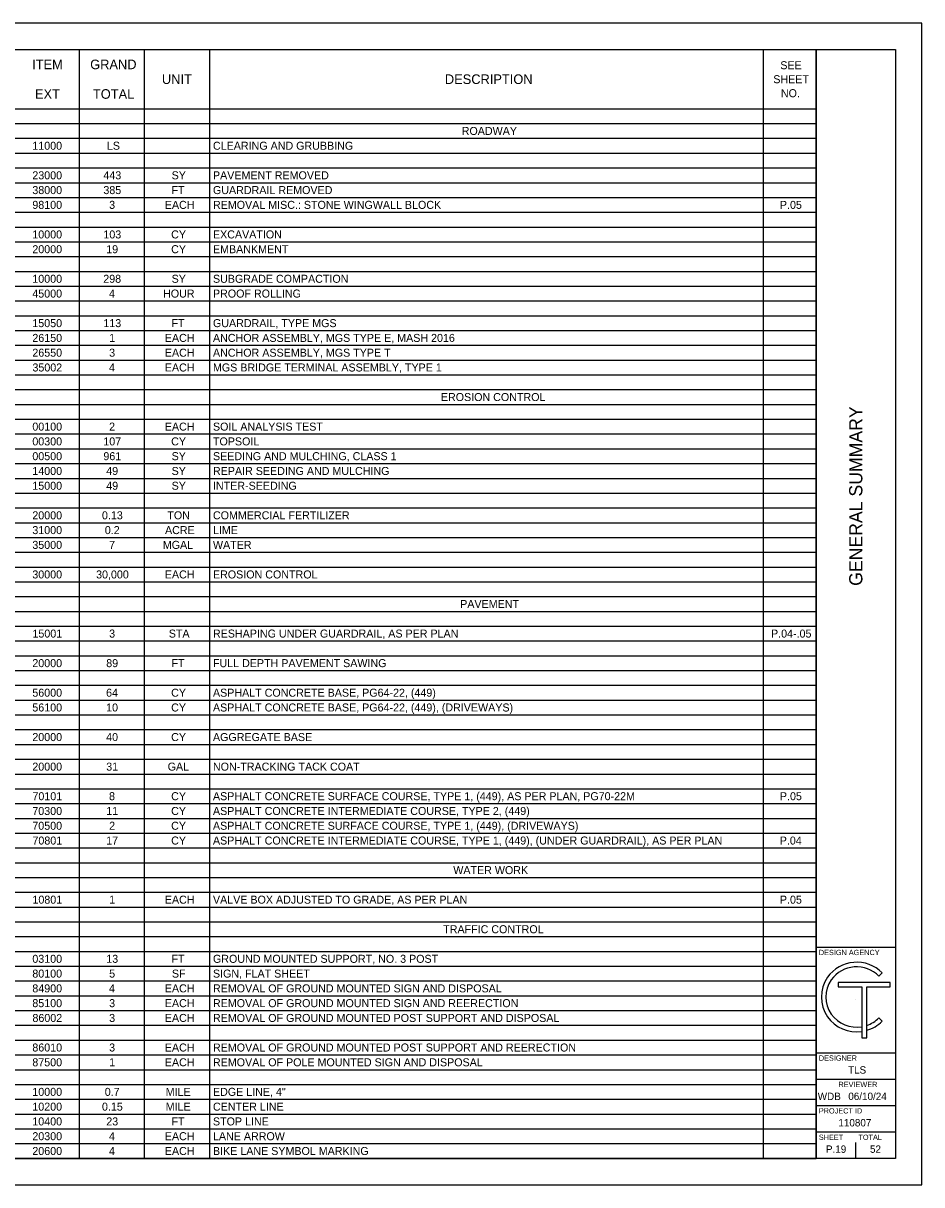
# Model space of a CAD drawing. Extents: x 0 to 34, y 0 to 22.
# Drawn here: x 16.98 to 34, y 0 to 22 of the extents above; entities that cross this region are included whole.
import ezdxf

# ---------------------------------------------------------------- set-up
doc = ezdxf.new("R2010")
doc.units = 0
for name, color, linetype in [('Default', 7, 'Continuous'), ('SH_Border', 7, 'Continuous'), ('SH_Cut_Line', 7, 'Continuous'), ('SH_Data', 7, 'Continuous'), ('SH_Text', 7, 'Continuous')]:
    doc.layers.add(name, color=color, linetype=linetype)

msp = doc.modelspace()

# ---------------------------------------------------------------- linework, layer by layer
at = {"layer": 'Default'}
for p, q in [((1.5, 21.5), (32, 21.5)), ((18.035, 21.5), (18.035, 0.5)), ((19.27, 21.5), (19.27, 0.5)), ((20.505, 21.5), (20.505, 0.5)), ((30.995, 21.5), (30.995, 0.5)), ((32, 21.5), (32, 0.5)), ((1.5, 20.38), (32, 20.38)), ((1.5, 20.1), (32, 20.1)), ((1.5, 19.82), (32, 19.82)), ((1.5, 19.54), (32, 19.54)), ((1.5, 19.26), (32, 19.26)), ((1.5, 18.98), (32, 18.98)), ((1.5, 18.7), (32, 18.7)), ((1.5, 18.42), (32, 18.42)), ((1.5, 18.14), (32, 18.14)), ((1.5, 17.86), (32, 17.86)), ((1.5, 17.58), (32, 17.58)), ((1.5, 17.3), (32, 17.3)), ((1.5, 17.02), (32, 17.02)), ((1.5, 16.74), (32, 16.74)), ((1.5, 16.46), (32, 16.46)), ((1.5, 16.18), (32, 16.18)), ((1.5, 15.9), (32, 15.9)), ((1.5, 15.62), (32, 15.62)), ((1.5, 15.34), (32, 15.34)), ((1.5, 15.06), (32, 15.06)), ((1.5, 14.78), (32, 14.78)), ((1.5, 14.5), (32, 14.5)), ((1.5, 14.22), (32, 14.22)), ((1.5, 13.94), (32, 13.94)), ((1.5, 13.66), (32, 13.66)), ((1.5, 13.38), (32, 13.38)), ((1.5, 13.1), (32, 13.1)), ((1.5, 12.82), (32, 12.82)), ((1.5, 12.54), (32, 12.54)), ((1.5, 12.26), (32, 12.26)), ((1.5, 11.98), (32, 11.98)), ((1.5, 11.7), (32, 11.7)), ((1.5, 11.42), (32, 11.42)), ((1.5, 11.14), (32, 11.14)), ((1.5, 10.86), (32, 10.86)), ((1.5, 10.58), (32, 10.58)), ((1.5, 10.3), (32, 10.3)), ((1.5, 10.02), (32, 10.02)), ((1.5, 9.74), (32, 9.74)), ((1.5, 9.46), (32, 9.46)), ((1.5, 9.18), (32, 9.18)), ((1.5, 8.9), (32, 8.9)), ((1.5, 8.62), (32, 8.62)), ((1.5, 8.34), (32, 8.34)), ((1.5, 8.06), (32, 8.06)), ((1.5, 7.78), (32, 7.78)), ((1.5, 7.5), (32, 7.5)), ((1.5, 7.22), (32, 7.22)), ((1.5, 6.94), (32, 6.94)), ((1.5, 6.66), (32, 6.66)), ((1.5, 6.38), (32, 6.38)), ((1.5, 6.1), (32, 6.1)), ((1.5, 5.82), (32, 5.82)), ((1.5, 5.54), (32, 5.54)), ((1.5, 5.26), (32, 5.26)), ((1.5, 4.98), (32, 4.98)), ((1.5, 4.7), (32, 4.7)), ((1.5, 4.42), (32, 4.42)), ((1.5, 4.14), (32, 4.14)), ((1.5, 3.86), (32, 3.86)), ((1.5, 3.58), (32, 3.58)), ((1.5, 3.3), (32, 3.3)), ((1.5, 3.02), (32, 3.02)), ((1.5, 2.74), (32, 2.74)), ((1.5, 2.46), (32, 2.46)), ((1.5, 2.18), (32, 2.18)), ((1.5, 1.9), (32, 1.9)), ((1.5, 1.62), (32, 1.62)), ((1.5, 1.34), (32, 1.34)), ((1.5, 1.06), (32, 1.06)), ((1.5, 0.78), (32, 0.78)), ((1.5, 0.5), (32, 0.5))]:
    msp.add_line(p, q, dxfattribs=at)
at = {"layer": 'SH_Border'}
for p, q in [((32, 0.5), (32, 21.5)), ((32, 4.5), (33.5, 4.5)), ((32, 2.5), (33.5, 2.5)), ((32, 2), (33.5, 2)), ((32, 1.5), (33.5, 1.5)), ((32, 1), (33.5, 1))]:
    msp.add_line(p, q, dxfattribs=at)
msp.add_lwpolyline([(1.5, 21.5), (33.5, 21.5), (33.5, 0.5), (1.5, 0.5)], close=True, dxfattribs=at)
at = {"layer": 'SH_Cut_Line'}
msp.add_lwpolyline([(0, 0), (34, 0), (34, 22), (0, 22)], close=True, dxfattribs=at)
at = {"layer": 'SH_Data'}
for p, q in [((32.75, 3.5), (32.75, 3.5)), ((32.375, 0.675), (32.375, 0.675)), ((32.75, 0.5), (32.75, 0.8))]:
    msp.add_line(p, q, dxfattribs=at)
at = {"layer": 'SH_Text'}
for p, q in [((33.249, 4.013), (33.187, 3.952)), ((33.249, 4.013), (33.187, 3.952)), ((33.402, 3.833), (32.414, 3.833)), ((32.414, 3.833), (32.414, 3.751)), ((32.414, 3.751), (32.863, 3.751)), ((32.863, 3.751), (32.863, 2.785)), ((32.956, 2.785), (32.956, 3.751)), ((32.956, 3.751), (33.402, 3.751)), ((33.402, 3.751), (33.402, 3.833)), ((33.187, 3.16), (33.249, 3.099)), ((33.187, 3.16), (33.249, 3.099)), ((32.863, 2.993), (32.863, 2.905)), ((32.863, 2.993), (32.863, 2.905)), ((32.956, 2.925), (32.956, 3.016)), ((32.956, 2.925), (32.956, 3.016)), ((32.863, 2.785), (32.956, 2.785))]:
    msp.add_line(p, q, dxfattribs=at)
msp.add_lwpolyline([(32.863, 3.751), (32.863, 2.785), (32.956, 2.785), (32.956, 3.751), (33.402, 3.751), (33.402, 3.833), (32.414, 3.833), (32.414, 3.751)], close=True, dxfattribs=at)
for centre, radius, start, end in [((32.766, 3.535), 0.68, 44.7027, 144.3276), ((32.766, 3.535), 0.68, 44.7027, 144.3276), ((32.766, 3.535), 0.593, 44.7362, 144.1102), ((32.766, 3.535), 0.593, 44.7362, 144.1102), ((32.764, 3.556), 0.666, 145.7329, 214.2671), ((32.764, 3.556), 0.666, 145.7329, 214.2671), ((32.764, 3.556), 0.579, 145.7266, 214.2734), ((32.764, 3.556), 0.579, 145.7266, 214.2734), ((32.766, 3.578), 0.68, 215.6724, 278.2613), ((32.766, 3.578), 0.68, 215.6724, 278.2613), ((32.766, 3.578), 0.593, 215.8898, 279.4882), ((32.766, 3.578), 0.593, 215.8898, 279.4882), ((32.766, 3.578), 0.593, 288.6992, 315.2638), ((32.766, 3.578), 0.593, 288.6992, 315.2638), ((32.766, 3.578), 0.68, 286.2291, 315.2973), ((32.766, 3.578), 0.68, 286.2291, 315.2973)]:
    msp.add_arc(centre, radius, start, end, dxfattribs=at)

# ---------------------------------------------------------------- texts
at = {"layer": 'Default'}
for s, height, p in [('ITEM', 0.1818, (17.145, 21.129)), ('GRAND', 0.1818, (18.245, 21.129)), ('SEE ', 0.1515, (31.32, 21.129)), ('UNIT', 0.1818, (19.604, 20.849)), ('DESCRIPTION', 0.18184, (24.965, 20.849)), ('SHEET ', 0.1515, (31.187, 20.864)), ('EXT', 0.1818, (17.199, 20.569)), ('TOTAL', 0.1818, (18.297, 20.569)), ('NO.', 0.1515, (31.331, 20.599)), ('ROADWAY', 0.1515, (25.284, 19.884)), ('11000', 0.1515, (17.149, 19.604)), ('LS', 0.1515, (18.562, 19.604)), ('CLEARING AND GRUBBING', 0.15153, (20.571, 19.604)), ('23000', 0.1515, (17.149, 19.044)), ('443', 0.1515, (18.495, 19.044)), ('SY', 0.1515, (19.788, 19.044)), ('PAVEMENT REMOVED', 0.15153, (20.571, 19.044)), ('38000', 0.1515, (17.149, 18.764)), ('385', 0.1515, (18.495, 18.764)), ('FT', 0.1515, (19.786, 18.764)), ('GUARDRAIL REMOVED', 0.15153, (20.571, 18.764)), ('98100', 0.1515, (17.149, 18.484)), ('3', 0.152, (18.604, 18.484)), ('EACH', 0.1515, (19.659, 18.484)), ('REMOVAL MISC.: STONE WINGWALL BLOCK', 0.15153, (20.571, 18.484)), ('P.05', 0.1515, (31.312, 18.484)), ('10000', 0.1515, (17.149, 17.924)), ('103', 0.1515, (18.495, 17.924)), ('CY', 0.1515, (19.779, 17.924)), ('EXCAVATION', 0.1515, (20.571, 17.924)), ('20000', 0.1515, (17.149, 17.644)), ('19', 0.1515, (18.549, 17.644)), ('CY', 0.1515, (19.779, 17.644)), ('EMBANKMENT', 0.1515, (20.571, 17.644)), ('10000', 0.1515, (17.149, 17.084)), ('298', 0.1515, (18.493, 17.084)), ('SY', 0.1515, (19.788, 17.084)), ('SUBGRADE COMPACTION', 0.15153, (20.571, 17.084)), ('45000', 0.1515, (17.149, 16.804)), ('4', 0.152, (18.601, 16.804)), ('HOUR', 0.1515, (19.626, 16.804)), ('PROOF ROLLING', 0.15153, (20.571, 16.804)), ('15050', 0.1515, (17.149, 16.244)), ('113', 0.1515, (18.495, 16.244)), ('FT', 0.1515, (19.786, 16.244)), ('GUARDRAIL, TYPE MGS', 0.15153, (20.571, 16.244)), ('26150', 0.1515, (17.149, 15.964)), ('1', 0.152, (18.604, 15.964)), ('EACH', 0.1515, (19.659, 15.964)), ('ANCHOR ASSEMBLY, MGS TYPE E, MASH 2016', 0.15153, (20.571, 15.964)), ('26550', 0.1515, (17.149, 15.684)), ('3', 0.152, (18.604, 15.684)), ('EACH', 0.1515, (19.659, 15.684)), ('ANCHOR ASSEMBLY, MGS TYPE T', 0.15153, (20.571, 15.684)), ('35002', 0.1515, (17.151, 15.404)), ('4', 0.152, (18.601, 15.404)), ('EACH', 0.1515, (19.659, 15.404)), ('MGS BRIDGE TERMINAL ASSEMBLY, TYPE 1', 0.15153, (20.571, 15.404)), ('EROSION CONTROL', 0.15153, (24.889, 14.844)), ('00100', 0.1515, (17.149, 14.284)), ('2', 0.152, (18.604, 14.284)), ('EACH', 0.1515, (19.659, 14.284)), ('SOIL ANALYSIS TEST', 0.15153, (20.571, 14.284)), ('00300', 0.1515, (17.149, 14.004)), ('107', 0.1515, (18.494, 14.004)), ('CY', 0.1515, (19.779, 14.004)), ('TOPSOIL', 0.1515, (20.571, 14.004)), ('00500', 0.1515, (17.149, 13.724)), ('961', 0.1515, (18.495, 13.724)), ('SY', 0.1515, (19.788, 13.724)), ('SEEDING AND MULCHING, CLASS 1', 0.15153, (20.571, 13.724)), ('14000', 0.1515, (17.149, 13.444)), ('49', 0.1515, (18.549, 13.444)), ('SY', 0.1515, (19.788, 13.444)), ('REPAIR SEEDING AND MULCHING', 0.15153, (20.571, 13.444)), ('15000', 0.1515, (17.149, 13.164)), ('49', 0.1515, (18.549, 13.164)), ('SY', 0.1515, (19.788, 13.164)), ('INTER-SEEDING', 0.15153, (20.571, 13.164)), ('20000', 0.1515, (17.149, 12.604)), ('0.13', 0.1515, (18.468, 12.604)), ('TON', 0.1515, (19.707, 12.604)), ('COMMERCIAL FERTILIZER', 0.15153, (20.571, 12.604)), ('31000', 0.1515, (17.149, 12.324)), ('0.2', 0.1515, (18.522, 12.324)), ('ACRE', 0.1515, (19.663, 12.324)), ('LIME', 0.1515, (20.571, 12.324)), ('35000', 0.1515, (17.149, 12.044)), ('7', 0.152, (18.603, 12.044)), ('MGAL', 0.1515, (19.621, 12.044)), ('WATER', 0.1515, (20.571, 12.044)), ('30000', 0.1515, (17.149, 11.484)), ('30,000', 0.1515, (18.357, 11.484)), ('EACH', 0.1515, (19.659, 11.484)), ('EROSION CONTROL', 0.15153, (20.571, 11.484)), ('PAVEMENT', 0.1515, (25.255, 10.924)), ('15001', 0.1515, (17.151, 10.364)), ('3', 0.152, (18.604, 10.364)), ('STA', 0.1515, (19.734, 10.364)), ('RESHAPING UNDER GUARDRAIL, AS PER PLAN', 0.15153, (20.571, 10.364)), ('P.04-.05', 0.1515, (31.144, 10.364)), ('20000', 0.1515, (17.149, 9.804)), ('89', 0.1515, (18.549, 9.804)), ('FT', 0.1515, (19.786, 9.804)), ('FULL DEPTH PAVEMENT SAWING', 0.15153, (20.571, 9.804)), ('56000', 0.1515, (17.149, 9.244)), ('64', 0.1515, (18.546, 9.244)), ('CY', 0.1515, (19.779, 9.244)), ('ASPHALT CONCRETE BASE, PG64-22, (449)', 0.15153, (20.571, 9.244)), ('56100', 0.1515, (17.149, 8.964)), ('10', 0.1515, (18.547, 8.964)), ('CY', 0.1515, (19.779, 8.964)), ('ASPHALT CONCRETE BASE, PG64-22, (449), (DRIVEWAYS)', 0.15153, (20.571, 8.964)), ('20000', 0.1515, (17.149, 8.404)), ('40', 0.1515, (18.547, 8.404)), ('CY', 0.1515, (19.779, 8.404)), ('AGGREGATE BASE', 0.15153, (20.571, 8.404)), ('20000', 0.1515, (17.149, 7.844)), ('31', 0.1515, (18.549, 7.844)), ('GAL', 0.1515, (19.713, 7.844)), ('NON-TRACKING TACK COAT', 0.15153, (20.571, 7.844)), ('70101', 0.1515, (17.151, 7.284)), ('8', 0.152, (18.602, 7.284)), ('CY', 0.1515, (19.779, 7.284)), ('ASPHALT CONCRETE SURFACE COURSE, TYPE 1, (449), AS PER PLAN, PG70-22M', 0.15153, (20.571, 7.284)), ('P.05', 0.1515, (31.312, 7.284)), ('70300', 0.1515, (17.149, 7.004)), ('11', 0.1515, (18.549, 7.004)), ('CY', 0.1515, (19.779, 7.004)), ('ASPHALT CONCRETE INTERMEDIATE COURSE, TYPE 2, (449)', 0.15153, (20.571, 7.004)), ('70500', 0.1515, (17.149, 6.724)), ('2', 0.152, (18.604, 6.724)), ('CY', 0.1515, (19.779, 6.724)), ('ASPHALT CONCRETE SURFACE COURSE, TYPE 1, (449), (DRIVEWAYS)', 0.15153, (20.571, 6.724)), ('ASPHALT CONCRETE INTERMEDIATE COURSE, TYPE 1, (449), (UNDER GUARDRAIL), AS PER PLAN', 0.15153, (20.571, 6.444)), ('70801', 0.1515, (17.151, 6.444)), ('17', 0.1515, (18.548, 6.444)), ('CY', 0.1515, (19.779, 6.444)), ('P.04', 0.1515, (31.309, 6.444)), ('WATER WORK', 0.1515, (25.124, 5.884)), ('10801', 0.1515, (17.151, 5.324)), ('1', 0.152, (18.604, 5.324)), ('EACH', 0.1515, (19.659, 5.324)), ('VALVE BOX ADJUSTED TO GRADE, AS PER PLAN', 0.15153, (20.571, 5.324)), ('P.05', 0.1515, (31.312, 5.324)), ('TRAFFIC CONTROL', 0.15153, (24.933, 4.764)), ('03100', 0.1515, (17.149, 4.204)), ('13', 0.1515, (18.55, 4.204)), ('FT', 0.1515, (19.786, 4.204)), ('GROUND MOUNTED SUPPORT, NO. 3 POST', 0.15153, (20.571, 4.204)), ('80100', 0.1515, (17.149, 3.924)), ('5', 0.152, (18.604, 3.924)), ('SF', 0.1515, (19.793, 3.924)), ('SIGN, FLAT SHEET', 0.15153, (20.571, 3.924)), ('84900', 0.1515, (17.149, 3.644)), ('4', 0.152, (18.601, 3.644)), ('EACH', 0.1515, (19.659, 3.644)), ('REMOVAL OF GROUND MOUNTED SIGN AND DISPOSAL', 0.15153, (20.571, 3.644)), ('85100', 0.1515, (17.149, 3.364)), ('3', 0.152, (18.604, 3.364)), ('EACH', 0.1515, (19.659, 3.364)), ('REMOVAL OF GROUND MOUNTED SIGN AND REERECTION', 0.15153, (20.571, 3.364)), ('86002', 0.1515, (17.151, 3.084)), ('3', 0.152, (18.604, 3.084)), ('EACH', 0.1515, (19.659, 3.084)), ('REMOVAL OF GROUND MOUNTED POST SUPPORT AND DISPOSAL', 0.15153, (20.571, 3.084)), ('86010', 0.1515, (17.149, 2.524)), ('3', 0.152, (18.604, 2.524)), ('EACH', 0.1515, (19.659, 2.524)), ('REMOVAL OF GROUND MOUNTED POST SUPPORT AND REERECTION', 0.15153, (20.571, 2.524)), ('87500', 0.1515, (17.149, 2.244)), ('1', 0.152, (18.604, 2.244)), ('EACH', 0.1515, (19.659, 2.244)), ('REMOVAL OF POLE MOUNTED SIGN AND DISPOSAL', 0.15153, (20.571, 2.244)), ('10000', 0.1515, (17.149, 1.684)), ('0.7', 0.1515, (18.521, 1.684)), ('MILE', 0.1515, (19.676, 1.684)), ('EDGE LINE, 4"', 0.15153, (20.571, 1.684)), ('10200', 0.1515, (17.149, 1.404)), ('0.15', 0.1515, (18.468, 1.404)), ('MILE', 0.1515, (19.676, 1.404)), ('CENTER LINE', 0.15153, (20.571, 1.404)), ('10400', 0.1515, (17.149, 1.124)), ('23', 0.1515, (18.55, 1.124)), ('FT', 0.1515, (19.786, 1.124)), ('STOP LINE', 0.1515, (20.571, 1.124)), ('20300', 0.1515, (17.149, 0.844)), ('4', 0.152, (18.601, 0.844)), ('EACH', 0.1515, (19.659, 0.844)), ('LANE ARROW', 0.1515, (20.571, 0.844)), ('20600', 0.1515, (17.149, 0.564)), ('4', 0.152, (18.601, 0.564)), ('EACH', 0.1515, (19.659, 0.564)), ('BIKE LANE SYMBOL MARKING', 0.15153, (20.571, 0.564))]:
    msp.add_text(s, height=height, dxfattribs=at).set_placement(p)
at = {"layer": 'SH_Data'}
msp.add_text('GENERAL SUMMARY', height=0.25, rotation=90, dxfattribs=at).set_placement((32.875, 11.344))
for s, height, p in [('DESIGN AGENCY', 0.1, (32.05, 4.35)), ('DESIGNER', 0.1, (32.05, 2.35)), ('TLS', 0.14, (32.603, 2.105)), ('REVIEWER', 0.1, (32.422, 1.85)), ('WDB', 0.14, (32.029, 1.605)), ('06/10/24', 0.14, (32.608, 1.605)), ('PROJECT ID', 0.1, (32.05, 1.35)), ('110807', 0.14, (32.42, 1.105)), ('SHEET', 0.1, (32.05, 0.85)), ('TOTAL', 0.1, (32.8, 0.85)), ('P.19', 0.14, (32.184, 0.605)), ('52', 0.14, (33.019, 0.605))]:
    msp.add_text(s, height=height, dxfattribs=at).set_placement(p)

doc.saveas('drawing.dxf')
